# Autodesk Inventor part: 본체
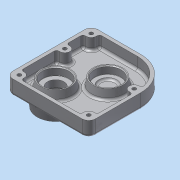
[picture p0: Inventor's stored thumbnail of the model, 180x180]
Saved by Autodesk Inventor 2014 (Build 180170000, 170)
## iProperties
Created: 2015-11
Part Number: 본체
Material: 알루미늄 6061
Document SubType Name: Modeling
Designer: dgall
Density: 2.71 g/cm^3
Appearance: 알루미늄 - 평지
Mass: 247.553 g
Surface Area: 389.424 cm^2
Volume: 91.3479 cm^3
Author: dgall
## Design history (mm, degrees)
sketch "스케치1"
  geometry: L1 (-50, 51.5)-(-50, -51.5); L2 (-50, -51.5)-(50, -51.5); L3 (50, -51.5)-(50, 11.5); L4 (10, 51.5)-(-50, 51.5); A1 r 40 centre (10, 11.5) between (50, 11.5) and (10, 51.5); 3 further points
  constraints: 8 end point, 2 midpoint, 2 parallel, 2 point on circle, 2 tangent, 1 centre point, 1 horizontal alignment, 1 perpendicular, 1 vertical, 1 vertical alignment
  dimensions: "d0" = 100 distance of L1.end L2.end; "d1" = 103 distance of L1.start L1.end; "d2" = 40 radius of A1
extrude "돌출1" new body sketch "스케치1" distance "d3" = 18; taper "d4" = 0 deg
node "작업 평면2"
sketch "스케치3"
  geometry: L1 (-50, 51.5)-(-50, -51.5) reference; L2 (10, 51.5)-(-50, 51.5) reference; L3 (50, -51.5)-(50, 11.5) reference; L4 (-50, -51.5)-(50, -51.5) reference; L5 (10, 47.5)-(-46, 47.5); L6 (-46, 47.5)-(-46, -47.5); L7 (-46, -47.5)-(46, -47.5); L8 (46, -47.5)-(46, 11.5); A1 r 40 centre (10, 11.5) between (50, 11.5) and (10, 51.5) reference; A2 r 36 centre (10, 11.5) between (46, 11.5) and (10, 47.5); 1 further point
  constraints: 8 end point, 2 point on circle, 1 centre point, 4 other
  dimensions: "d15" = 4 distance between parallel lines of L5 L2
extrude "돌출2" cut sketch "스케치3" distance "d16" = 18; taper "d17" = 0 deg
sketch "스케치4"
  geometry: L1 (-50, 51.5)-(-50, -51.5) reference; L2 (-50, -51.5)-(50, -51.5) reference; L3 (50, -51.5)-(50, 11.5) reference; L4 (10, 51.5)-(-50, 51.5) reference; C1 r 6 at (-42, 43.5); C2 r 6 at (-42, -43.5); C3 r 6 at (42, -43.5); C4 r 6 at (42, 11.5); C5 r 6 at (-42, 11.5); 1 further point
  constraints: 5 centre point, 4 equal radius, 3 vertical alignment, 2 horizontal alignment
  dimensions: "d18" = 8 distance from line of C1.centre L1; "d19" = 8 distance from line of L3 C3.centre; "d20" = 8 distance from line of C3.centre L2; "d21" = 12 diameter of C2; "d22" = 8 distance from line of C1.centre L4; "d23" = 55 distance of C4.centre C3.centre
extrude "돌출3" join sketch "스케치4" distance "d24" = 18; taper "d25" = 0 deg
sketch "스케치5"
  geometry: L1 (-50, 51.5)-(-50, -51.5) reference; L2 (-50, -51.5)-(50, -51.5) reference; C1 r 20 at (10, 11.5); 1 further point
  constraints: 1 centre point
  dimensions: "d26" = 60 distance from line of C1.centre L1; "d27" = 63 distance from line of L2 C1.centre; "d28" = 40 diameter of C1
extrude "돌출4" join sketch "스케치5" distance "d29" = 11; taper "d30" = -10 deg
sketch "스케치6"
  geometry: C1 r 18.06 at (0, 0) reference; C2 r 16 at (0, 0); C3 r 11 at (0, 0); 1 further point
  constraints: 2 centre point, 2 coincident
  dimensions: "d31" = 32 diameter of C2; "d32" = 22 diameter of C3
extrude "돌출5" cut sketch "스케치6" distance "d33" = 9; taper "d34" = 0 deg
extrude "돌출6" cut sketch "스케치6" distance "d35" = 11; taper "d36" = 0 deg
sketch "스케치7"
  geometry: L1 (-50, -51.5)-(50, -51.5) reference; L2 (-50, 51.5)-(-50, -51.5) reference; C1 r 20 at (-20, -21.5); 1 further point
  constraints: 1 centre point
  dimensions: "d37" = 30 distance from line of L1 C1.centre; "d38" = 30 distance from line of C1.centre L2; "d39" = 40 diameter of C1
extrude "돌출7" join sketch "스케치7" distance "d40" = 11; taper "d41" = -10 deg
sketch "스케치8"
  geometry: L1 (50, 51.5)-(50, -51.5) reference; L2 (50, -51.5)-(-50, -51.5) reference; C1 r 25 at (20, -21.5); 1 further point
  constraints: 1 centre point
  dimensions: "d52" = 50 diameter of C1; "d53" = 30 distance from line of L1 C1.centre; "d54" = 30 distance from line of C1.centre L2
extrude "돌출8" join sketch "스케치8" distance "d42" = 15; taper "d43" = -10 deg
node "작업 평면3"
sketch "스케치9"
  geometry: L1 (15, 48.06)-(15, 11.94) reference; L2 (-15, 30)-(15, 30); L3 (-15, 44)-(-4, 44); L4 (-4, 44)-(-4, 42); L5 (-4, 42)-(-2, 42); L6 (-2, 42)-(-2, 40); L7 (-2, 40)-(6, 40); L8 (6, 40)-(6, 46); L9 (6, 46)-(15, 46); L10 (-15, 7.645)-(-15, 52.355) reference; L11 (-15, 44)-(-15, 30); L12 (15, 46)-(15, 30); 2 further points
  constraints: 20 end point, 7 parallel, 2 midpoint, 2 perpendicular, 1 point on line, 1 vertical alignment
  dimensions: "d45" = 32 diameter of L9 L2; "d46" = 20 diameter of L7 L2; "d47" = 24 diameter of L5 L2; "d50" = 2 distance between parallel lines of L6 L4; "d51" = 9 distance between parallel lines of L1 L8; "d55" = 28 diameter of L3 L2; "d56" = 11 distance between parallel lines of L4 L10
revolve "회전1" sketch "스케치9" stored, may be unused: angle "d57" = 90 deg
hole "구멍1" diameter "d60" = 4.5; stored, may be unused: countersink angle "d64" = 90 deg, drill point angle "d66" = 118 deg; dims "d58" = 10, "d59" = 10, "d61" = 6, "d62" = 8, "d63" = 4.4, "d65" = 8
hole "구멍2" diameter "d69" = 4.5; stored, may be unused: countersink angle "d73" = 90 deg, drill point angle "d75" = 118 deg; dims "d67" = 10, "d68" = 10, "d70" = 6, "d71" = 8, "d72" = 4.4, "d74" = 8
hole "구멍3" diameter "d78" = 4.5; stored, may be unused: countersink angle "d82" = 90 deg, drill point angle "d84" = 118 deg; dims "d76" = 10, "d77" = 10, "d79" = 6, "d80" = 8, "d81" = 4.4, "d83" = 8
hole "구멍4" diameter "d87" = 4.5; stored, may be unused: countersink angle "d91" = 90 deg, drill point angle "d93" = 118 deg; dims "d85" = 10, "d86" = 10, "d88" = 6, "d89" = 8, "d90" = 4.4, "d92" = 8
hole "구멍5" diameter "d96" = 4.5; stored, may be unused: countersink angle "d100" = 90 deg, drill point angle "d102" = 118 deg; dims "d94" = 10, "d95" = 10, "d97" = 6, "d98" = 8, "d99" = 4.4, "d101" = 8
sketch "스케치10"
  geometry: C1 r 14 at (0, 0) reference; 2 further points
  constraints: 1 vertical alignment
  dimensions: "d103" = 18 distance of C1.centre point (0, 18)
hole "구멍6" sketch "스케치10" at (0, 18) diameter "d104" = 2.459; stored, may be unused: countersink angle "d108" = 90 deg, drill point angle "d110" = 118 deg; dims "d105" = 8, "d106" = 8, "d107" = 4.4, "d109" = 10
sketch "스케치11"
  geometry: L1 (50, 51.5)-(50, -51.5) reference; L2 (-10, 51.5)-(50, 51.5) reference; 2 further points
  constraints: 1 other
  dimensions: "d114" = 40 distance from line of L1 point (10, 31.5); "d115" = 20 distance from line of point (10, 31.5) L2
feature "엠보싱1" sketch "스케치11" dims "d15" = 4, "d116" = 0.5, "d117" = 0
fillet "모깎기1" dims "d118" = 8
fillet "모깎기4" dims "d121" = 0.3
fillet "모깎기5" dims "d122" = 3
fillet "모깎기6" dims "d123" = 3
fillet "모깎기7" dims "d124" = 3
fillet "모깎기8" dims "d125" = 3
fillet "모깎기9" dims "d126" = 3
chamfer "모따기1" distance "d127" = 1; stored, may be unused: second distance "d128" = 2, angle "d129" = 45 deg
fillet "모깎기10" dims "d130" = 3
fillet "모깎기11" dims "d131" = 3
fillet "모깎기12" dims "d132" = 0.3
node "솔리드1"
pattern_circular "원형 패턴1" dims angle "d112" = 360 deg
node "투영된 루프1"
other parameters: "d14" = -14
